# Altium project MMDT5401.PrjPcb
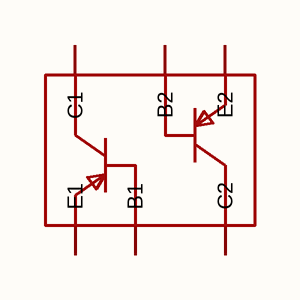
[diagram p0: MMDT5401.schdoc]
1 sheet, 1 parts. Net scope: global (net labels, ports and power ports of the same name join across sheets).

## Sheet MMDT5401.schdoc
size 127 x 101 mm

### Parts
Q?  mmdt5401(range:100-300)  [SC-70-6_L2.1-W1.3-P0.65-LS2.3-BR]  (value not drawn)

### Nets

Not connected (* = marked no-connect by the designer): Q? 1(E1) 2(B1) 3(C2) 4(E2) 5(B2) 6(C1)

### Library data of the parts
Q? = mmdt5401(range:100-300): 晶体管类型:PNP;集电极电流(Ic):200mA;集射极击穿电压(Vceo):150V;耗散功率(Pd):200mW;直流电流增益(hFE):50;; Manufacturer: CJ(江苏长电/长晶); AddInBom: yes; ModelId: 083e1ef491294aaf9be49ca98df3f498; ModelTransform: 90.551,82.677,0,0,0,0,0,0,0; type: PNP; Current - Collector(Ic): 200mA; Collector - Emitter Voltage VCEO: 150V; Pd - Power Dissipation: 200mW; DC Current Gain: 50; Transition frequency(fT): 100MHz; Current - Collector Cutoff: 50nA; Vce Saturation(VCE(sat)): 200mV; Emitter-Base Voltage(Vebo): 5V; Number: 2个PNP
